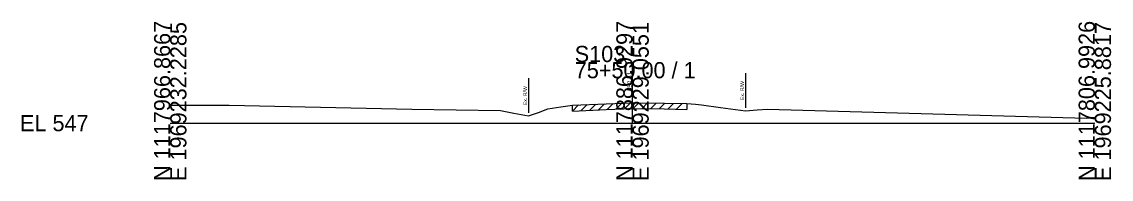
# Model space of a CAD drawing. Extents: x -26 to 163, y -10 to 24018.
# Drawn here: x -25.7 to 162.8, y 23490.3 to 23517.5 of the extents above; entities that cross this region are included whole.
import ezdxf

# ---------------------------------------------------------------- set-up
doc = ezdxf.new("R2010")
doc.units = 0
for name, color, linetype in [('RD_GPK_XS_Cell', 7, 'Continuous'), ('RD_XS_ExGround', 7, 'Continuous'), ('RD_XS_ExPaveRet', 7, 'Continuous'), ('RD_XS_ExRW', 7, 'Continuous'), ('RD_XS_TX_Elev_EX', 7, 'Continuous')]:
    doc.layers.add(name, color=color, linetype=linetype)

msp = doc.modelspace()

# ---------------------------------------------------------------- linework, layer by layer
at = {"layer": 'RD_GPK_XS_Cell'}
for p, q in [((80, 23500), (80, 23510.56)), ((0, 23500), (80, 23500)), ((80, 23500), (160, 23500))]:
    msp.add_line(p, q, dxfattribs=at)
at = {"layer": 'RD_XS_ExGround'}
msp.add_lwpolyline([(0, 23503.1), (10.17, 23503.1), (41.81, 23502.44), (57.16, 23502.19), (59.45, 23501.75), (61.99, 23501.27), (63.71, 23501.87), (65.35, 23502.46), (67.59, 23502.8), (69.61, 23503.1), (75.45, 23503.34), (80, 23503.51), (80.31, 23503.52), (85.5, 23503.45), (89.42, 23503.37), (90.88, 23503.26), (91.96, 23503.17), (95.25, 23502.73), (99.55, 23502.14), (101.58, 23502.3), (103.35, 23502.43), (113.56, 23502.11), (158.55, 23500.86), (160, 23501.02)], dxfattribs=at)
at = {"layer": 'RD_XS_ExPaveRet'}
for p, q in [((69.61, 23502.1), (70.65, 23503.14)), ((69.61, 23502.1), (69.61, 23503.1)), ((71.11, 23502.16), (72.15, 23503.2)), ((72.61, 23502.22), (73.65, 23503.27)), ((74.11, 23502.29), (75.15, 23503.33)), ((75.45, 23502.34), (80, 23502.51)), ((75.61, 23502.35), (76.65, 23503.39)), ((77.11, 23502.4), (78.15, 23503.44)), ((78.61, 23502.46), (79.65, 23503.5)), ((80, 23502.51), (80.31, 23502.52)), ((80.11, 23502.51), (81.11, 23503.51)), ((80.31, 23502.52), (85.5, 23502.45)), ((81.61, 23502.5), (82.6, 23503.49)), ((83.11, 23502.48), (84.1, 23503.47)), ((84.61, 23502.46), (85.6, 23503.44)), ((86.11, 23502.43), (87.09, 23503.42)), ((87.61, 23502.41), (88.59, 23503.39)), ((89.42, 23503.37), (89.42, 23502.37)), ((69.61, 23502.1), (75.45, 23502.34)), ((85.5, 23502.45), (89.42, 23502.37))]:
    msp.add_line(p, q, dxfattribs=at)
at = {"layer": 'RD_XS_ExRW'}
for p, q in [((99.55, 23508.64), (99.55, 23502.64)), ((61.99, 23507.77), (61.99, 23501.77))]:
    msp.add_line(p, q, dxfattribs=at)

# ---------------------------------------------------------------- texts
at = {"layer": 'RD_GPK_XS_Cell'}
for s, p in [('N 1117966.8667', (0, 23490)), ('E 1969232.2285', (2.8, 23490)), ('N 1117886.9297', (80, 23490)), ('E 1969229.0551', (82.8, 23490)), ('N 1117806.9926', (160, 23490)), ('E 1969225.8817', (162.8, 23490))]:
    msp.add_text(s, height=2.8, rotation=90, dxfattribs=at).set_placement(p)
for s, p in [('S103', (70, 23510.56)), ('75+50.00 / 1', (70, 23507.76)), ('EL 547', (-26, 23498.6))]:
    msp.add_text(s, height=2.8, dxfattribs=at).set_placement(p)
at = {"layer": 'RD_XS_ExRW'}
for p in [(61.74, 23503.11), (99.3, 23503.98)]:
    msp.add_text('Ex. R/W ', height=0.65, rotation=90, dxfattribs=at).set_placement(p)
at = {"layer": 'RD_XS_TX_Elev_EX'}
msp.add_text('550.51', height=0.8, rotation=90, dxfattribs=at).set_placement((79.9, 23505.51))

doc.saveas('drawing.dxf')
